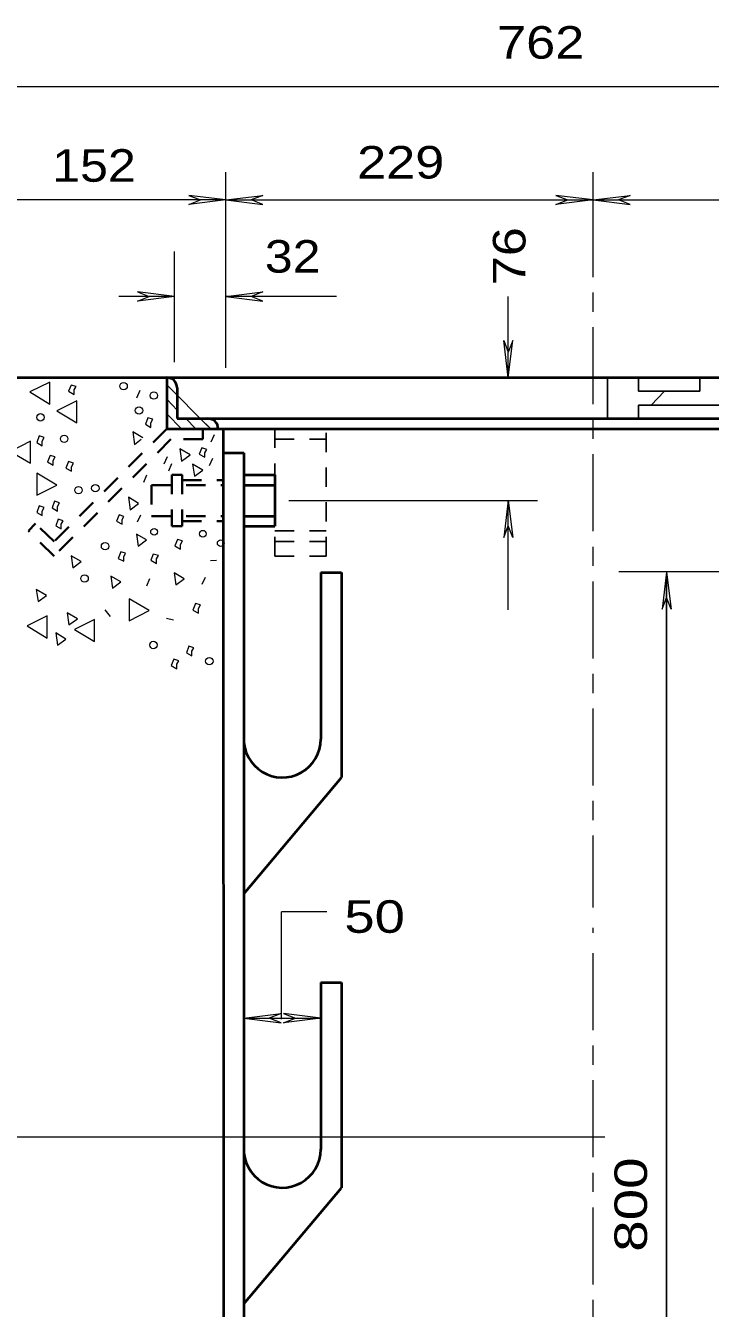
# Model space of a CAD drawing. Extents: x 312583 to 312854, y 144419 to 144597.
# Drawn here: x 312710.02 to 312726, y 144495.47 to 144525.44 of the extents above; entities that cross this region are included whole.
import ezdxf

# ---------------------------------------------------------------- set-up
doc = ezdxf.new("R2010")
doc.units = 0
doc.header["$LTSCALE"] = 0.3
doc.linetypes.add('LONG_DASH_SHORT_DASH', pattern=[9.9, 6, -1.2, 1.5, -1.2])
doc.linetypes.add('SHORT_DASHED', pattern=[2.7, 1.5, -1.2])
doc.layers.add('1', color=7, linetype='Continuous', lineweight=40)
doc.layers.add('2', color=7, linetype='Continuous', lineweight=13)

msp = doc.modelspace()

# ---------------------------------------------------------------- linework, layer by layer
at = {"layer": '1', "linetype": 'LONG_DASH_SHORT_DASH', "lineweight": 13}
for p, q in [((312723.2592, 144522.0199), (312723.2592, 144521.3682)), ((312723.2592, 144521.3682), (312723.2592, 144504.8389)), ((312723.2592, 144504.3635), (312723.2592, 144504.2485)), ((312723.2592, 144503.7732), (312723.2592, 144493.7605))]:
    msp.add_line(p, q, dxfattribs=at)
at = {"layer": '1'}
for p, q in [((312709.3672, 144517.2205), (312733.0878, 144517.2205)), ((312713.3155, 144517.2205), (312713.3155, 144516.0245)), ((312713.5608, 144516.9829), (312713.5608, 144516.2622)), ((312713.5608, 144516.2622), (312732.8425, 144516.2622)), ((312713.3155, 144516.0245), (312733.0878, 144516.0245)), ((312714.6342, 144516.0245), (312714.6495, 144471.2205)), ((312714.6342, 144515.4649), (312715.1172, 144515.4649)), ((312715.1172, 144515.4649), (312715.1172, 144483.9165)), ((312715.1172, 144514.9435), (312715.8378, 144514.9435)), ((312715.1172, 144514.7059), (312715.8378, 144514.7059)), ((312715.8378, 144514.9435), (312715.8378, 144513.7475)), ((312715.1172, 144513.9852), (312715.8378, 144513.9852)), ((312715.1172, 144513.7475), (312715.8378, 144513.7475)), ((312716.9112, 144512.6665), (312716.9112, 144508.7719)), ((312716.9112, 144512.6665), (312717.3942, 144512.6665)), ((312717.3942, 144512.6665), (312717.3942, 144507.8749)), ((312715.1172, 144505.1609), (312717.3942, 144507.8749)), ((312714.6418, 144504.3635), (312714.6418, 144503.7349)), ((312715.1172, 144504.3635), (312715.1172, 144503.7349)), ((312716.9112, 144503.0832), (312716.9112, 144499.1885)), ((312716.9112, 144503.0832), (312717.3942, 144503.0832)), ((312717.3942, 144503.0832), (312717.3942, 144498.2915)), ((312715.1172, 144495.5775), (312717.3942, 144498.2915))]:
    msp.add_line(p, q, dxfattribs=at)
at = {"layer": '1', "linetype": 'SHORT_DASHED', "lineweight": 35}
for p, q in [((312711.5215, 144517.2205), (312712.0045, 144517.2205)), ((312713.3155, 144516.0245), (312710.6858, 144513.3872)), ((312714.1588, 144516.0245), (312714.1588, 144515.7792)), ((312713.4152, 144515.7792), (312710.6858, 144513.0499)), ((312714.1588, 144515.7792), (312713.4152, 144515.7792)), ((312712.9628, 144514.7059), (312712.9628, 144513.9852)), ((312712.9628, 144514.7059), (312714.6342, 144514.7059)), ((312713.4382, 144514.9435), (312713.4382, 144513.7475)), ((312713.4382, 144514.9435), (312713.6758, 144514.9435)), ((312713.6758, 144514.9435), (312713.6758, 144513.7475)), ((312713.6758, 144514.8209), (312714.6342, 144514.8209)), ((312710.2565, 144513.8089), (312710.0878, 144513.6402)), ((312710.6858, 144513.3872), (312710.2565, 144513.8089)), ((312712.9628, 144513.9852), (312714.6342, 144513.9852)), ((312713.6758, 144513.8625), (312714.6342, 144513.8625)), ((312710.6858, 144513.0499), (312710.0878, 144513.6402)), ((312713.4382, 144513.7475), (312713.6758, 144513.7475))]:
    msp.add_line(p, q, dxfattribs=at)
at = {"layer": '1', "lineweight": 25}
for p, q in [((312723.6042, 144516.2622), (312723.6042, 144517.2205)), ((312724.3248, 144516.8985), (312724.3248, 144517.2205)), ((312725.7585, 144516.8985), (312725.7585, 144517.2205)), ((312724.3248, 144516.8985), (312725.7585, 144516.8985)), ((312724.6238, 144516.5765), (312724.9382, 144516.8985)), ((312724.3248, 144516.5765), (312731.5085, 144516.5765)), ((312724.3248, 144516.2622), (312724.3248, 144516.5765))]:
    msp.add_line(p, q, dxfattribs=at)
at = {"layer": '1', "lineweight": 13}
for p, q in [((312712.6868, 144516.9139), (312712.6102, 144516.7375)), ((312714.4195, 144515.8789), (312714.3428, 144515.7102)), ((312712.5642, 144515.6565), (312712.7175, 144515.7792)), ((312713.3232, 144515.3652), (312713.2465, 144515.1965)), ((312714.3812, 144515.3269), (312714.3045, 144515.1582)), ((312713.4305, 144515.2042), (312713.3538, 144515.0355)), ((312712.8478, 144514.9359), (312712.7712, 144514.7672)), ((312712.7022, 144514.0082), (312712.6255, 144513.8395)), ((312714.3352, 144512.9425), (312714.4808, 144512.9502)), ((312724.9842, 144512.5975), (312724.9842, 144483.8935)), ((312724.9842, 144483.9779), (312724.9842, 144512.5975)), ((312712.9168, 144512.5209), (312712.8402, 144512.3445)), ((312714.2125, 144512.5515), (312714.1358, 144512.3829)), ((312711.8742, 144511.7925), (312711.9968, 144511.6392)), ((312713.3078, 144511.6009), (312713.4765, 144511.5625))]:
    msp.add_line(p, q, dxfattribs=at)
at = {"layer": '1', "linetype": 'SHORT_DASHED', "lineweight": 25}
for p, q in [((312715.8378, 144516.0245), (312715.8378, 144514.9435)), ((312717.0338, 144513.0499), (312717.0338, 144516.0245)), ((312715.8378, 144515.7792), (312717.0338, 144515.7792)), ((312715.8378, 144513.0499), (312715.8378, 144513.7475)), ((312715.8378, 144513.6402), (312717.0338, 144513.6402)), ((312715.8378, 144513.3872), (312717.0338, 144513.3872)), ((312715.8378, 144513.0499), (312717.0338, 144513.0499))]:
    msp.add_line(p, q, dxfattribs=at)
at = {"layer": '1', "lineweight": 13}
for points in [[(312710.5862, 144516.5995), (312710.5862, 144517.1132), (312710.1185, 144516.8832)], [(312711.1535, 144516.9292), (312711.1995, 144517.0135), (312711.0845, 144517.0442), (312711.0232, 144516.8985), (312711.1535, 144516.8219)], [(312711.2148, 144516.1625), (312711.2148, 144516.6762), (312710.7548, 144516.4385)], [(312712.9475, 144516.1625), (312712.9935, 144516.2469), (312712.8785, 144516.2775), (312712.8172, 144516.1319), (312712.9475, 144516.0552)], [(312710.1338, 144515.2195), (312710.1338, 144515.7332), (312709.6662, 144515.4955)], [(312710.4098, 144515.7332), (312710.4558, 144515.8175), (312710.3408, 144515.8559), (312710.2872, 144515.7025), (312710.4098, 144515.6259)], [(312714.2048, 144515.4649), (312714.2508, 144515.5415), (312714.1358, 144515.5799), (312714.0745, 144515.4265), (312714.2048, 144515.3575)], [(312710.6628, 144515.2809), (312710.7088, 144515.3652), (312710.5938, 144515.3959), (312710.5325, 144515.2502), (312710.6628, 144515.1735)], [(312713.6605, 144515.2655), (312713.8598, 144515.4112), (312713.6222, 144515.5569)], [(312710.2872, 144514.9895), (312710.2872, 144514.4759), (312710.7548, 144514.7059)], [(312711.0922, 144515.1352), (312711.1382, 144515.2195), (312711.0232, 144515.2579), (312710.9618, 144515.1045), (312711.0922, 144515.0355)], [(312713.9672, 144514.9129), (312714.1588, 144515.0585), (312713.9212, 144515.1965)], [(312712.4645, 144514.1309), (312712.6562, 144514.2765), (312712.4262, 144514.4222)], [(312710.4098, 144514.1002), (312710.4558, 144514.1845), (312710.3408, 144514.2229), (312710.2872, 144514.0695), (312710.4098, 144514.0005)], [(312710.7702, 144514.2075), (312710.8162, 144514.2919), (312710.6935, 144514.3302), (312710.6398, 144514.1769), (312710.7702, 144514.1002)], [(312710.8545, 144513.7935), (312710.9005, 144513.8702), (312710.7855, 144513.9085), (312710.7242, 144513.7552), (312710.8545, 144513.6862)], [(312712.2728, 144513.9009), (312712.3188, 144513.9775), (312712.2038, 144514.0159), (312712.1425, 144513.8625), (312712.2728, 144513.7935)], [(312712.6485, 144513.2799), (312712.8402, 144513.4255), (312712.6102, 144513.5635)], [(312713.6375, 144513.3182), (312713.6835, 144513.4025), (312713.5685, 144513.4332), (312713.5072, 144513.2875), (312713.6375, 144513.2109)], [(312711.1228, 144512.7739), (312711.3222, 144512.9195), (312711.0845, 144513.0575)], [(312712.3112, 144513.0345), (312712.3572, 144513.1189), (312712.2422, 144513.1495), (312712.1808, 144512.9962), (312712.3112, 144512.9272)], [(312713.0778, 144512.9809), (312713.1238, 144513.0652), (312713.0012, 144513.0959), (312712.9475, 144512.9502), (312713.0778, 144512.8735)], [(312712.0505, 144512.2985), (312712.2422, 144512.4442), (312712.0122, 144512.5822)], [(312713.5302, 144512.3752), (312713.7218, 144512.5209), (312713.4918, 144512.6589)], [(312710.3178, 144511.9842), (312710.5095, 144512.1299), (312710.2718, 144512.2679)], [(312712.4415, 144512.0532), (312712.4415, 144511.5395), (312712.9092, 144511.7772)], [(312711.0308, 144511.4399), (312711.2302, 144511.5855), (312710.9925, 144511.7235)], [(312714.0592, 144511.8232), (312714.1052, 144511.9075), (312713.9902, 144511.9382), (312713.9288, 144511.7849), (312714.0592, 144511.7159)], [(312710.5248, 144511.1332), (312710.5248, 144511.6545), (312710.0572, 144511.4169)], [(312711.6288, 144511.0565), (312711.6288, 144511.5702), (312711.1612, 144511.3325)], [(312710.7702, 144510.9645), (312710.9618, 144511.1102), (312710.7242, 144511.2559)], [(312713.9058, 144510.8265), (312713.9518, 144510.9032), (312713.8292, 144510.9415), (312713.7755, 144510.7882), (312713.9058, 144510.7192)], [(312713.5532, 144510.5199), (312713.5992, 144510.6042), (312713.4842, 144510.6425), (312713.4228, 144510.4892), (312713.5532, 144510.4125)]]:
    msp.add_lwpolyline(points, close=True, dxfattribs=at)
msp.add_lwpolyline([(312712.7558, 144515.8099), (312712.5258, 144515.9479), (312712.5642, 144515.6565)], dxfattribs=at)
at = {"layer": '1'}
for points in [[(312714.6418, 144504.2179), (312714.6418, 144504.0952), (312714.6418, 144503.7349)], [(312715.1172, 144504.2179), (312715.1172, 144504.0952), (312715.1172, 144503.7349)]]:
    msp.add_lwpolyline(points, dxfattribs=at)
at = {"layer": '1', "lineweight": 13}
for centre, radius in [((312712.3097, 144517.0181), 0.0865), ((312713.016, 144516.7987), 0.0865), ((312712.6691, 144516.4508), 0.0865), ((312710.371, 144516.2898), 0.0865), ((312710.923, 144515.7876), 0.0865), ((312711.2565, 144514.5878), 0.0865), ((312711.6503, 144514.6338), 0.0865), ((312713.0203, 144513.6153), 0.0784), ((312714.1588, 144513.5712), 0.0784), ((312711.8765, 144513.2787), 0.0865), ((312714.5767, 144513.3489), 0.0784), ((312711.3993, 144512.5264), 0.0865), ((312713.0054, 144510.971), 0.0865), ((312714.3097, 144510.5944), 0.0865)]:
    msp.add_circle(centre, radius, dxfattribs=at)
at = {"layer": '1'}
for centre, radius, start, end in [((312713.3184, 144516.98), 0.2396, 0, 90), ((312714.2767, 144516.0217), 0.2396, 0, 90), ((312716.0132, 144508.7743), 0.8984, 178.12864, 359.96943), ((312716.0132, 144499.1909), 0.8984, 178.12864, 359.96943)]:
    msp.add_arc(centre, radius, start, end, dxfattribs=at)
at = {"layer": '2'}
for p, q in [((312708.8842, 144524.0209), (312737.6955, 144524.0209)), ((312714.6955, 144517.4505), (312714.6955, 144522.0199)), ((312714.6955, 144521.3682), (312708.9455, 144521.3682)), ((312713.8292, 144521.4755), (312714.1052, 144521.3682)), ((312714.6955, 144521.3682), (312713.8292, 144521.4755)), ((312713.8292, 144521.2609), (312714.1052, 144521.3682)), ((312714.6955, 144521.3682), (312713.8292, 144521.2609)), ((312714.6955, 144521.3682), (312715.5618, 144521.4755)), ((312714.6955, 144521.3682), (312715.5618, 144521.2609)), ((312715.5618, 144521.4755), (312715.2858, 144521.3682)), ((312715.5618, 144521.2609), (312715.2858, 144521.3682)), ((312722.4005, 144521.4755), (312722.6765, 144521.3682)), ((312723.2668, 144521.3682), (312722.4005, 144521.4755)), ((312722.4005, 144521.2609), (312722.6765, 144521.3682)), ((312723.2668, 144521.3682), (312722.4005, 144521.2609)), ((312723.2668, 144521.3682), (312724.1332, 144521.4755)), ((312723.2668, 144521.3682), (312724.1332, 144521.2609)), ((312724.1332, 144521.4755), (312723.8572, 144521.3682)), ((312724.1332, 144521.2609), (312723.8572, 144521.3682)), ((312713.4995, 144517.5809), (312713.4995, 144520.1645)), ((312712.6332, 144519.2215), (312712.9092, 144519.1142)), ((312713.4995, 144519.1142), (312712.6332, 144519.2215)), ((312714.6955, 144519.1142), (312715.5618, 144519.2215)), ((312715.5618, 144519.2215), (312715.2858, 144519.1142)), ((312713.4995, 144519.1142), (312712.1962, 144519.1142)), ((312712.6332, 144519.0069), (312712.9092, 144519.1142)), ((312713.4995, 144519.1142), (312712.6332, 144519.0069)), ((312717.2792, 144519.1142), (312714.6955, 144519.1142)), ((312714.6955, 144519.1142), (312715.5618, 144519.0069)), ((312715.5618, 144519.0069), (312715.2858, 144519.1142)), ((312721.2888, 144517.2205), (312721.2888, 144519.1101)), ((312721.1815, 144518.0869), (312721.2888, 144517.8109)), ((312721.2888, 144517.2205), (312721.1815, 144518.0869)), ((312721.3962, 144518.0869), (312721.2888, 144517.8109)), ((312721.2888, 144517.2205), (312721.3962, 144518.0869)), ((312714.2738, 144516.0859), (312713.3232, 144517.0442)), ((312713.5608, 144516.4615), (312713.3232, 144516.7069)), ((312713.6605, 144516.0245), (312713.3232, 144516.3619)), ((312713.9978, 144516.0245), (312713.7602, 144516.2622)), ((312714.3428, 144516.0245), (312714.0975, 144516.2622)), ((312716.1675, 144514.3455), (312721.9712, 144514.3455)), ((312721.2888, 144514.3455), (312721.1815, 144513.4792)), ((312721.2888, 144511.7925), (312721.2888, 144514.3455)), ((312721.2888, 144514.3455), (312721.3962, 144513.4792)), ((312721.1815, 144513.4792), (312721.2888, 144513.7552)), ((312721.3962, 144513.4792), (312721.2888, 144513.7552)), ((312728.7178, 144512.6819), (312723.8648, 144512.6819)), ((312724.9842, 144512.6742), (312724.8768, 144511.8079)), ((312724.9842, 144512.6742), (312725.0915, 144511.8079)), ((312724.8768, 144511.8079), (312724.9842, 144512.0839)), ((312725.0915, 144511.8079), (312724.9842, 144512.0839)), ((312717.0568, 144504.7392), (312715.9988, 144504.7392)), ((312715.9988, 144502.2322), (312715.9988, 144504.7392)), ((312715.1172, 144502.2552), (312715.9835, 144502.3625)), ((312715.1172, 144502.2552), (312716.9112, 144502.2552)), ((312715.1172, 144502.2552), (312715.9835, 144502.1479)), ((312715.9835, 144502.3625), (312715.7075, 144502.2552)), ((312715.9835, 144502.1479), (312715.7075, 144502.2552)), ((312716.0448, 144502.3625), (312716.3208, 144502.2552)), ((312716.9112, 144502.2552), (312716.0448, 144502.3625)), ((312716.0448, 144502.1479), (312716.3208, 144502.2552)), ((312716.9112, 144502.2552), (312716.0448, 144502.1479)), ((312723.5428, 144499.4722), (312704.1462, 144499.4722))]:
    msp.add_line(p, q, dxfattribs=at)
msp.add_lwpolyline([(312714.6955, 144521.3682), (312723.2668, 144521.3682), (312731.9455, 144521.3682)], dxfattribs=at)

# ---------------------------------------------------------------- texts
for s, width, p in [('762 ', 1.2, (312721.0271, 144524.6698)), ('152 ', 1.15, (312710.6445, 144521.7947)), ('229 ', 1.2, (312717.7598, 144521.8694)), ('32 ', 1.15, (312715.6057, 144519.6709)), ('50 ', 1.25, (312717.4621, 144504.2476))]:
    msp.add_text(s, height=0.76, dxfattribs=dict(at, width=width)).set_placement(p)
for s, width, p in [('76 ', 1.2, (312721.6898, 144519.3775)), ('800 ', 1.3, (312724.5266, 144496.7956))]:
    msp.add_text(s, height=0.76, rotation=90, dxfattribs=dict(at, width=width)).set_placement(p)

doc.saveas('drawing.dxf')
